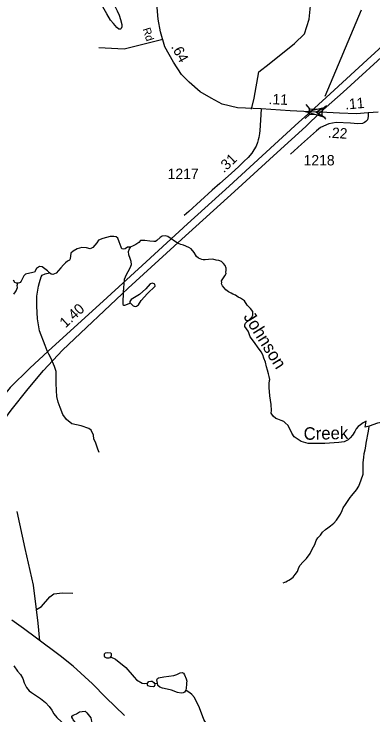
# Model space of a CAD drawing. Extents: x 2056842 to 2160602, y 826753 to 1016856.
# Drawn here: x 2095813 to 2100119, y 891536 to 899934 of the extents above; entities that cross this region are included whole.
import ezdxf

# ---------------------------------------------------------------- set-up
doc = ezdxf.new("R2010")
doc.units = 0
for name, color, linetype in [('Exist Hydrographic Creek Single Shore', 7, 'Continuous'), ('Exist Hydrographic Creek Single Shore Label', 7, 'Continuous'), ('Exist Hydrographic Misc Water Feature', 7, 'Continuous'), ('Exist Road Non-System Type 51', 7, 'Continuous'), ('Exist Road Primary Interstate Divided Center Attributed', 7, 'Continuous'), ('Exist Road Primary Interstate Mileage Hundredths English Label', 7, 'Continuous'), ('Exist Road Secondary Mileage Hundredths English Label', 7, 'Continuous'), ('Exist Road Secondary Structure Standard Bridge Attributed CELL', 7, 'Continuous'), ('Exist Road Secondary Structure Standard Bridge CELL', 7, 'Continuous'), ('Exist Road Secondary Type 41 Attributed', 7, 'Continuous'), ('Exist Road Secondary Type 51 Attributed', 7, 'Continuous'), ('Exist Road Secondary Type 51 Label', 7, 'Continuous'), ('Exist Road Secondary Type 51 Number Label', 7, 'Continuous')]:
    doc.layers.add(name, color=color, linetype=linetype)

msp = doc.modelspace()

# ---------------------------------------------------------------- linework, layer by layer
at = {"layer": 'Exist Hydrographic Creek Single Shore'}
for points in [[(2097215.8, 897145.7), (2097194, 897141.6), (2097175.9, 897140.6), (2097146, 897119.4), (2097122.3, 897115.7), (2097106, 897119.5), (2097097.3, 897139.4), (2097076.1, 897204.3), (2097058.6, 897246.7), (2097039.9, 897262.9), (2097011.2, 897270.4), (2096967.6, 897268.9), (2096879, 897246.5), (2096826.6, 897222.8), (2096806.6, 897194), (2096758, 897135.4), (2096728.1, 897120.4), (2096680.7, 897131.6), (2096625.8, 897136.6), (2096569.6, 897121.7), (2096522.2, 897094.2), (2096496, 897068), (2096488.3, 897001.3), (2096478.5, 896985.5), (2096456.6, 896973.4), (2096432.5, 896953.3), (2096405, 896930.7), (2096373.8, 896892), (2096318.9, 896830.8), (2096280.2, 896814.6), (2096260.3, 896817.1), (2096237.8, 896833.3)], [(2098344.4, 896919.3), (2098324.5, 896943.3), (2098300.4, 896967.1), (2098268.2, 896982.9), (2098236.2, 896986.8), (2098196.4, 896996.8), (2098144.1, 896992.7), (2098104.3, 896988.6), (2098080.4, 896988.4), (2098064.4, 896992.3), (2098026.7, 897008.3), (2098001.7, 897029.5), (2097973, 897078.2), (2097938.1, 897119.4), (2097910.6, 897138.1), (2097845.8, 897163.5), (2097813.8, 897171.4), (2097773.8, 897189.3), (2097659.9, 897266.7), (2097626.2, 897276.7), (2097588.8, 897272.9), (2097566.3, 897257.9), (2097525.7, 897218.7), (2097509.8, 897210.5), (2097489.8, 897210.6), (2097441.6, 897212.3), (2097383, 897220.5), (2097330.6, 897220.5), (2097309.7, 897197.9), (2097273.8, 897173.7), (2097235.9, 897153.9), (2097215.8, 897145.7)], [(2096237.8, 896833.3), (2096215.3, 896858.3), (2096151.7, 896905.7), (2096120.5, 896910.7), (2096084.4, 896887), (2096059.4, 896842.1), (2096002, 896830.8), (2095949.6, 896817.1), (2095931.2, 896795.7), (2095909.4, 896755.7), (2095897.4, 896731.7), (2095885.2, 896715.6), (2095877.3, 896711.5), (2095857.5, 896709.6)], [(2100074.8, 894994.2), (2100026.5, 894984.3), (2100037.8, 895054.7), (2100002, 895034.7), (2099970, 895010.5), (2099942.3, 894990.4), (2099918.1, 894962.3), (2099900.5, 894934.1), (2099872.6, 894888.1), (2099846.7, 894856.2), (2099820, 894833.5), (2099773.8, 894808.6), (2099710.2, 894798.6), (2099540.6, 894788.6), (2099342.2, 894787.3), (2099257.4, 894812.3), (2099175.1, 894869.7), (2099143.9, 894913.4), (2099103.2, 895003.3), (2099064.3, 895037.7), (2099049.6, 895050.7), (2099015.9, 895065.7), (2098977.9, 895079.6), (2098953.5, 895088.4), (2098919.8, 895117.1), (2098897.4, 895150.8), (2098899.9, 895185.8), (2098898.6, 895257.4), (2098883.7, 895361), (2098874.9, 895460.8), (2098872.4, 895507), (2098877.4, 895543.2), (2098879.9, 895555.7), (2098872.4, 895592.9), (2098866.5, 895624.9), (2098852.3, 895668.8), (2098842.3, 895706.8), (2098828, 895762.8), (2098809.6, 895810.8), (2098797.7, 895850.7), (2098777.4, 895886.6), (2098733.4, 895946.6), (2098705.3, 895986.5), (2098675.1, 896030.5), (2098646.9, 896066.2), (2098628.9, 896116.1), (2098622.8, 896136.2), (2098580.5, 896190), (2098581.8, 896211.2), (2098590.5, 896230), (2098624.2, 896261.2), (2098646.6, 896281.1), (2098664.3, 896302.4), (2098676.6, 896324.8), (2098678.1, 896350.3), (2098678.2, 896370.3), (2098647.9, 896406.2), (2098610.5, 896447.4), (2098576.8, 896498.6), (2098529.4, 896529.8), (2098503.2, 896541), (2098471.6, 896565.6), (2098439.3, 896577.7), (2098418.4, 896590.9), (2098384.7, 896607.2), (2098353.2, 896631.3), (2098333.3, 896655.4), (2098315.1, 896679), (2098303.1, 896703.2), (2098305.1, 896719.3), (2098302.9, 896739), (2098318.8, 896763.3), (2098342.9, 896799.2), (2098356.6, 896827.2), (2098352.6, 896839.4), (2098356.6, 896859.3), (2098358.5, 896887.2), (2098344.4, 896919.3)], [(2095857.5, 896709.6), (2095841.4, 896707.6), (2095821.2, 896715.6), (2095807.4, 896743.4)], [(2101016.2, 895024), (2100985, 895075.2), (2100957.6, 895095.1), (2100886.5, 895111.4), (2100796.5, 895141.6), (2100655.6, 895214), (2100629.7, 895231.4), (2100586.1, 895256.4), (2100544.9, 895275.1), (2100513.7, 895276.4), (2100471.3, 895256.4), (2100422.7, 895211.5), (2100379, 895154), (2100320.4, 895086.6), (2100308.4, 895071.7), (2100289.7, 895056.7), (2100251, 895043), (2100172.4, 895031.7), (2100074.8, 894994.2)], [(2095811.7, 892124), (2095854, 892062.2), (2095890, 892022.3), (2095918.3, 891974.4), (2095936.4, 891922.4), (2095964.5, 891864.5), (2095996.7, 891824.6), (2096024.8, 891806.7), (2096072.7, 891774.9), (2096131, 891735.1), (2096191.1, 891687.2), (2096235.3, 891639.4), (2096267.3, 891593.5), (2096292.3, 891550.8), (2096328.5, 891504.7), (2096380.9, 891452.2), (2096424.7, 891422.3), (2096467.9, 891404.2)]]:
    msp.add_lwpolyline(points, dxfattribs=at)
at = {"layer": 'Exist Hydrographic Misc Water Feature'}
msp.add_line((2097500, 891911.5), (2097532.4, 891915.3), dxfattribs=at)
for points in [[(2096916.7, 900067.3), (2096947.6, 900084.4), (2096961.5, 900095.1), (2096976.4, 900096.2), (2096987.1, 900088.7), (2097019.1, 900036.4), (2097051.1, 899971.3), (2097074.6, 899922.1), (2097088.5, 899868.8), (2097104.5, 899810), (2097106.6, 899781.2), (2097099.2, 899758.8), (2097090.6, 899751.3), (2097071.4, 899753.4), (2097045.8, 899771.6), (2097006.3, 899821.8), (2096969, 899861.3), (2096925.2, 899938.2), (2096880.4, 900020.4), (2096879.3, 900036.4), (2096890, 900053.5), (2096916.7, 900067.3)], [(2097209.6, 896468.9), (2097138.5, 896440.2), (2097127.2, 896442.6), (2097122.3, 896458.9), (2097122.3, 896471.4), (2097127.7, 896599.7), (2097131.6, 896651.6), (2097133.5, 896699.6), (2097139.2, 896755.7), (2097161.2, 896811.7), (2097183.1, 896847.8), (2097204.8, 896891.9), (2097220.6, 896933.9), (2097216.7, 896969.9), (2097204.4, 897005.9), (2097188.4, 897049.8), (2097186.2, 897089.8), (2097198.1, 897121.8), (2097215.9, 897145.8)], [(2096833.7, 894680.9), (2096819.5, 894720.9), (2096793.3, 894790.8), (2096771.4, 894842.7), (2096765.2, 894886.7), (2096738, 894947.1), (2096711.8, 894968.3), (2096618.3, 894998.5), (2096504.8, 895026), (2096442.4, 895077.2), (2096400, 895137.1), (2096366.3, 895218.5), (2096342.6, 895282.1), (2096326.4, 895353.3), (2096323.9, 895423.2), (2096317.6, 895511.8), (2096317.6, 895581.7), (2096317.6, 895649.1), (2096300.6, 895711.2), (2096276.4, 895767.1), (2096260.2, 895807), (2096230.2, 895858.9), (2096212, 895898.9), (2096185.9, 895960.7), (2096116.8, 896140.3), (2096093.1, 896281.4), (2096086.5, 896432.3), (2096086.3, 896464.4), (2096086.1, 896496.4), (2096087.9, 896552.4), (2096105.6, 896674.4), (2096117.4, 896716.4), (2096139.3, 896784.6), (2096151.7, 896803.4), (2096185.4, 896822.1), (2096237.8, 896833.3)], [(2095810.1, 896579.5), (2095831.8, 896603.7), (2095839.8, 896615.7), (2095853.7, 896655.7), (2095851.7, 896679.6), (2095857.4, 896709.7)], [(2097209.6, 896468.9), (2097240.8, 896437.7), (2097264.5, 896430.2), (2097281.9, 896433.9), (2097305.6, 896448.9), (2097338.1, 896500.1), (2097412.9, 896584.9), (2097506.5, 896674.8), (2097501.5, 896696), (2097472.8, 896711), (2097445.3, 896702.3), (2097395.4, 896642.4), (2097316.9, 896572.5), (2097218.3, 896512.5), (2097202.1, 896488.8), (2097203.3, 896478.8), (2097209.6, 896468.9)], [(2099042.3, 893120), (2099062.2, 893128), (2099074.1, 893132.1), (2099094.2, 893142.2), (2099110.2, 893150.2), (2099130.1, 893162.3), (2099160.2, 893186.4), (2099183.8, 893218.4), (2099211.9, 893256.5), (2099231.6, 893304.6), (2099245.7, 893332.6), (2099277.3, 893364.8), (2099321.4, 893410.8), (2099365.1, 893471), (2099388.8, 893523.1), (2099422.9, 893579.1), (2099438.7, 893627.1), (2099458.6, 893659.2), (2099488.3, 893691.3), (2099512.3, 893725.5), (2099550, 893757.4), (2099576.1, 893777.6), (2099610.1, 893801.6), (2099649.9, 893833.8), (2099681.9, 893869.9), (2099729.6, 893940), (2099751.4, 893984.1), (2099763.3, 894016.1), (2099787.5, 894056.2), (2099815.1, 894092.3), (2099845.1, 894140.4), (2099864.8, 894164.5), (2099920.5, 894234.6), (2099950.7, 894278.7), (2099978.4, 894354.8), (2100002.8, 894422.9), (2100002.8, 894475.3), (2100001.5, 894561.4), (2100009, 894620.1), (2100013.4, 894666.8), (2100025.1, 894710.8), (2100035.2, 894754.9), (2100038.9, 894790.9), (2100066.5, 894935), (2100074.3, 894991), (2100074.8, 894994.2)], [(2096970.3, 892231.3), (2096964.1, 892221.3), (2096950.4, 892216.3), (2096926.7, 892217.6), (2096903, 892227.6), (2096899.2, 892241.3), (2096899.2, 892267.5), (2096911.7, 892278.8), (2096936.6, 892283.7), (2096971.6, 892280), (2096977.8, 892272.5), (2096980.3, 892253.8), (2096976.6, 892241.3), (2096970.3, 892231.3)], [(2096970.3, 892231.3), (2097029, 892206.4), (2097156.2, 892105.3), (2097253.5, 891990.2), (2097282.2, 891956.5), (2097350.8, 891916.5), (2097377, 891911.5), (2097413.9, 891917.8)], [(2097532.4, 891915.3), (2097526.2, 891956.5), (2097532.4, 891972.7), (2097546.2, 891982.7), (2097609.8, 891993.9), (2097668.4, 892002.7), (2097728.3, 892007.7), (2097764.5, 892020.1), (2097804.4, 892041.4), (2097831.8, 892043.9), (2097848, 892037.6), (2097858, 892017.6), (2097879.2, 891969), (2097884.2, 891940.3), (2097883, 891921.5), (2097880.5, 891904.1), (2097876.7, 891855.4), (2097873, 891832.9)], [(2097500, 891911.5), (2097501.2, 891895.3), (2097493.8, 891876.6), (2097482.5, 891872.9), (2097445.1, 891875.3), (2097418.9, 891884.1), (2097412.7, 891897.8), (2097413.9, 891917.8)], [(2097413.9, 891917.8), (2097428.9, 891936.5), (2097452.6, 891942.8), (2097468.8, 891940.3), (2097491.3, 891926.5), (2097500, 891911.5)], [(2097873, 891832.9), (2097865.5, 891820.4), (2097856.8, 891807.9), (2097843, 891801.7), (2097816.8, 891798), (2097775.7, 891806.7), (2097703.3, 891831.7), (2097650.9, 891846.6), (2097592.3, 891859.1), (2097562.4, 891869.1), (2097539.9, 891890.3), (2097532.4, 891915.3)], [(2098868.1, 890918.8), (2098820.8, 890945.3), (2098764.6, 890989.1), (2098688.5, 891055), (2098610.4, 891118.6), (2098530, 891198.4), (2098457.8, 891244.2), (2098399.8, 891276.2), (2098343.7, 891307.9), (2098279.8, 891327.6), (2098217.6, 891351.5), (2098171.7, 891371.5), (2098151.7, 891387.3), (2098121.5, 891431.2), (2098091.4, 891483.1), (2098063, 891556.8), (2098031, 891640.8), (2098000.6, 891694.6), (2097976.4, 891744.6), (2097944.3, 891780.4), (2097920.4, 891800.6), (2097900.3, 891812.5), (2097873, 891832.9)], [(2096518.3, 891490.2), (2096506.9, 891510.9), (2096508.1, 891522.1), (2096521.9, 891532.1), (2096561.8, 891550.8), (2096600.5, 891572.1), (2096629.1, 891578.3), (2096665.3, 891579.6), (2096687.8, 891559.6), (2096732.7, 891503.4), (2096737.7, 891476), (2096746.4, 891446), (2096738.9, 891432.3), (2096720.2, 891424.8), (2096702.7, 891423.5), (2096684, 891412.3), (2096657.8, 891399.8), (2096632.9, 891397.3), (2096605.4, 891403.6), (2096574.3, 891422.3), (2096550.6, 891447.2), (2096524.4, 891479.7), (2096518.3, 891490.2)]]:
    msp.add_lwpolyline(points, dxfattribs=at)
at = {"layer": 'Exist Road Non-System Type 51'}
for points in [[(2098661.6, 898795.7), (2098695.4, 898924), (2098749, 899240), (2098874.2, 899335.4), (2099178, 899579.9), (2099295.7, 899694.7), (2099355.3, 899873.5), (2099391, 900234.3), (2099408.9, 900639.7)], [(2097596.3, 899628.7), (2097132.9, 899512.8), (2096829, 899530.7)], [(2096083.5, 892798.5), (2096047.7, 893090.7), (2095944.9, 893530.4), (2095849.6, 893974.6)], [(2096083.5, 892798.5), (2096143, 892834.3), (2096241.4, 892950.5), (2096289, 892989.3), (2096396.3, 892998.2), (2096518.4, 892995.3)], [(2096122.1, 892424.4), (2096104.3, 892634.5), (2096083.5, 892798.5)]]:
    msp.add_lwpolyline(points, dxfattribs=at)
at = {"layer": 'Exist Road Primary Interstate Divided Center Attributed'}
for points in [[(2103600.7, 902632.7), (2103289.4, 902345), (2102970.9, 902051.5), (2102555.2, 901669.9), (2102213.3, 901354.8), (2101753.5, 900939), (2100980.6, 900231.5), (2100459.7, 899759.8), (2100051.2, 899387.1), (2099654.4, 899021.7), (2099369.7, 898762.5)], [(2099487.6, 898757.1), (2099760.5, 898998.3), (2100355.3, 899542), (2101025.6, 900154), (2101811.1, 900874.2), (2102278.1, 901297.2), (2102621.8, 901610.5), (2103163.4, 902105.5), (2103660.8, 902561.3)], [(2099369.7, 898762.5), (2099231.5, 898636.4), (2098788.8, 898235), (2098392.9, 897871.3), (2097895.4, 897421.2), (2097399.6, 896964), (2096929.9, 896539.1), (2096224.5, 895894.6), (2096001.4, 895689.4), (2095768.3, 895458.9), (2095590.2, 895246.5), (2095439.9, 895041.3), (2095272.6, 894774.8), (2095166.4, 894573.2), (2095017, 894243.7), (2094892.9, 893941.3), (2094738.1, 893566.8), (2094600.8, 893244)], [(2094683.8, 893192), (2094819.1, 893509.2), (2094975.6, 893865.7), (2095110.6, 894142.9), (2095290.6, 894463.4), (2095439.9, 894702.8), (2095603.7, 894951.2), (2095777.3, 895187.1), (2095982.5, 895444.5), (2096168.7, 895664.2), (2096394.6, 895907.2), (2097181.8, 896648.9), (2097827, 897237.6), (2098457.7, 897806.5), (2098968.8, 898274.6), (2099312.5, 898587.8), (2099487.6, 898757.1)]]:
    msp.add_lwpolyline(points, dxfattribs=at)
at = {"layer": 'Exist Road Secondary Mileage Hundredths English Label'}
msp.add_line((2099547.1, 898948.8), (2099981, 899982.8), dxfattribs=at)
at = {"layer": 'Exist Road Secondary Structure Standard Bridge Attributed CELL'}
msp.add_lwpolyline([(2099545.4, 898693), (2099311.9, 898763.6), (2099549.4, 898819.2), (2099433.8, 898759.7)], close=True, dxfattribs=at)
at = {"layer": 'Exist Road Secondary Structure Standard Bridge CELL'}
for p, q in [((2099312.2, 898849.7), (2099359, 898798.9)), ((2099509.9, 898792.3), (2099560.7, 898839)), ((2099305.3, 898681.7), (2099356, 898728.4)), ((2099507.1, 898723.4), (2099553.8, 898672.6))]:
    msp.add_line(p, q, dxfattribs=at)
msp.add_lwpolyline([(2099359, 898798.9), (2099509.9, 898792.7), (2099507, 898722.1), (2099356, 898728.4)], close=True, dxfattribs=at)
at = {"layer": 'Exist Road Secondary Type 41 Attributed'}
for points in [[(2098777.6, 898798.8), (2098768.7, 898664.2), (2098761.3, 898539.5), (2098756.6, 898501.4), (2098748.5, 898456.2), (2098741.3, 898426.6), (2098732.9, 898394), (2098716.4, 898352.7), (2098690.1, 898308.2), (2098664.7, 898268.2), (2098622, 898215.6), (2098571.7, 898167.2), (2098509.3, 898107.6), (2098418.9, 898022.4), (2098283, 897901.8), (2098191.2, 897824.8), (2097910.3, 897567.5), (2097854, 897519)], [(2100062.6, 898750.4), (2100062.6, 898705.3), (2100053.4, 898664.9), (2100032.6, 898645.3), (2100018.7, 898633.7), (2099993.3, 898623.3), (2099935.6, 898617.5), (2099847.8, 898624.5), (2099675.6, 898634.9), (2099590.1, 898618.7), (2099490.8, 898573.6), (2099441.1, 898536.1), (2099259.7, 898374.3), (2099131.5, 898254.2)]]:
    msp.add_lwpolyline(points, dxfattribs=at)
at = {"layer": 'Exist Road Secondary Type 51 Attributed'}
for points in [[(2098777.6, 898798.8), (2098495.8, 898808.2), (2098310.7, 898853.1), (2098177.8, 898926.8), (2098044.8, 899002.3), (2097913.7, 899117.4), (2097823, 899208.2), (2097724.2, 899355.6), (2097621.8, 899542.5), (2097569.7, 899718.7), (2097543.6, 899870.6), (2097529.3, 900010.8), (2097532.8, 900183.4), (2097551.7, 900308.4), (2097591.2, 900448.6), (2097672.1, 900689.5), (2097696.3, 900823.4), (2097698.1, 901021.2), (2097685.6, 901154.2), (2097637, 901269.2), (2097584.5, 901381.1)], [(2099369.7, 898762.5), (2099127.2, 898773.1), (2098777.6, 898798.8)], [(2099487.6, 898757.1), (2099433.8, 898759.7), (2099369.7, 898762.5)], [(2100062.6, 898750.4), (2099920.5, 898737.7), (2099718.7, 898745.7), (2099487.6, 898757.1)], [(2100180.5, 898759.6), (2100062.6, 898750.4)], [(2097138.4, 891528.9), (2096914.6, 891746.9), (2096755.2, 891910.1), (2096521.7, 892119.2), (2096366, 892244.4), (2096081.9, 892454.9), (2095928.5, 892571.2), (2095788.4, 892670.3)]]:
    msp.add_lwpolyline(points, dxfattribs=at)

# ---------------------------------------------------------------- texts
at = {"layer": 'Exist Hydrographic Creek Single Shore Label'}
for s, rotation, p in [('Johnson', 302.03967, (2098560.1, 896308.1)), ('Creek', 1.13861, (2099288.7, 894831.8))]:
    msp.add_text(s, height=150, rotation=rotation, dxfattribs=at).set_placement(p)
at = {"layer": 'Exist Road Primary Interstate Mileage Hundredths English Label'}
msp.add_text('1.40', height=125, rotation=42.41653, dxfattribs=at).set_placement((2096429.1, 896166.2))
at = {"layer": 'Exist Road Secondary Mileage Hundredths English Label'}
for s, rotation, p in [('.64', 298.70962, (2097693, 899542.6)), ('.11', 357.28006, (2098864.5, 898855.3)), ('.11', 5.11036, (2099790.4, 898788.8)), ('.22', 356.54338, (2099577.1, 898453)), ('.31', 43.30437, (2098330.1, 898024.6))]:
    msp.add_text(s, height=125, rotation=rotation, dxfattribs=at).set_placement(p)
at = {"layer": 'Exist Road Secondary Type 51 Label'}
msp.add_text('Rd.', height=95, rotation=286.96378, dxfattribs=at).set_placement((2097355.3, 899755.2))
at = {"layer": 'Exist Road Secondary Type 51 Number Label'}
for s, p in [('1218', (2099286.9, 898120)), ('1217', (2097655.9, 897957.1))]:
    msp.add_text(s, height=125, dxfattribs=at).set_placement(p)

doc.saveas('drawing.dxf')
